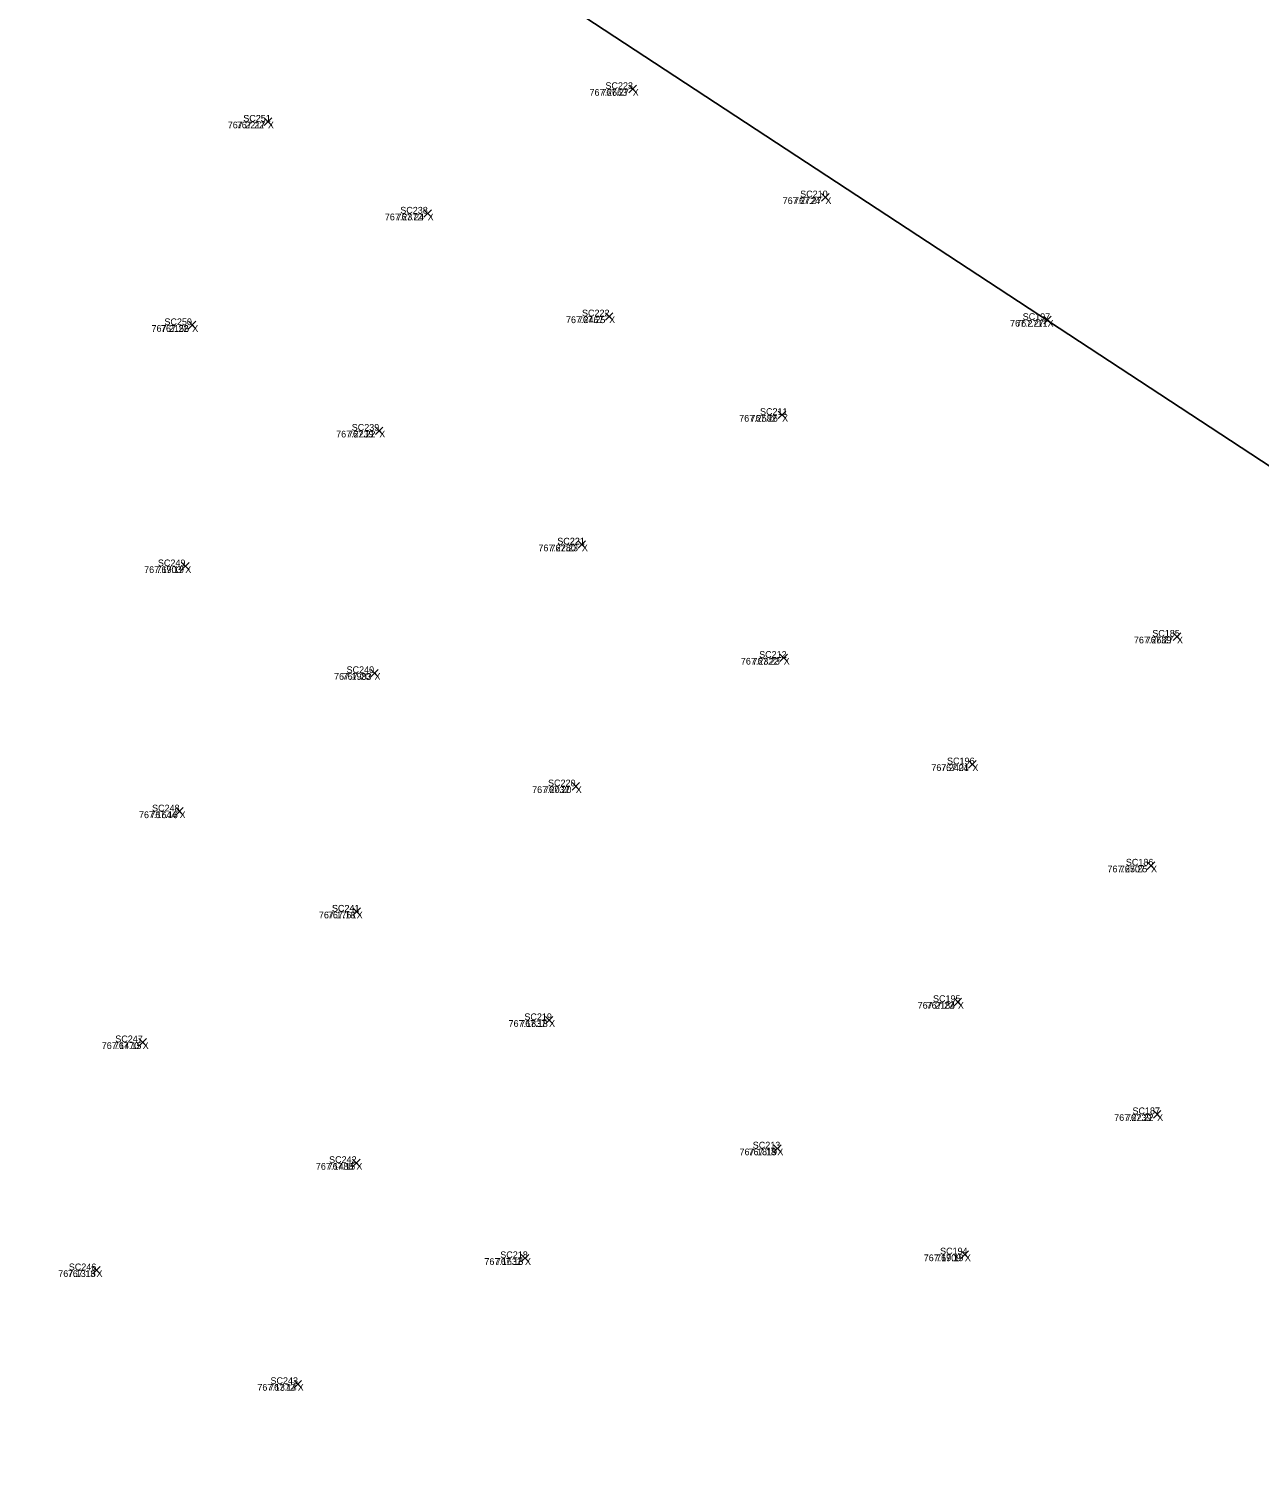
# Model space of a CAD drawing. Extents: x 1845019 to 1877956, y 680444 to 701081.
# Drawn here: x 1857662.57 to 1857673.54, y 694264.34 to 694277.24 of the extents above; entities that cross this region are included whole.
import ezdxf

# ---------------------------------------------------------------- set-up
doc = ezdxf.new("R2010")
doc.units = 0
for name, color, linetype in [('SV_X_CL_Survey_20', 7, 'Continuous'), ('SV_X_Random_Point', 7, 'Continuous'), ('SV_X_Text_Comment', 7, 'Continuous'), ('SV_X_Text_Elevation', 7, 'Continuous'), ('SV_X_Text_Name', 7, 'Continuous')]:
    doc.layers.add(name, color=color, linetype=linetype)

msp = doc.modelspace()

# ---------------------------------------------------------------- linework, layer by layer
at = {"layer": 'SV_X_CL_Survey_20'}
msp.add_line((1856038.267, 695346.314), (1858797.327, 693536.085), dxfattribs=at)
at = {"layer": 'SV_X_Random_Point'}
for p, q in [((1857667.919, 694276.675), (1857667.986, 694276.742)), ((1857667.919, 694276.742), (1857667.986, 694276.675)), ((1857667.919, 694276.675), (1857667.986, 694276.742)), ((1857667.919, 694276.742), (1857667.986, 694276.675)), ((1857664.666, 694276.384), (1857664.733, 694276.451)), ((1857664.666, 694276.451), (1857664.733, 694276.384)), ((1857664.666, 694276.384), (1857664.733, 694276.451)), ((1857664.666, 694276.451), (1857664.733, 694276.384)), ((1857669.638, 694275.709), (1857669.705, 694275.776)), ((1857669.638, 694275.776), (1857669.705, 694275.709)), ((1857669.638, 694275.709), (1857669.705, 694275.776)), ((1857669.638, 694275.776), (1857669.705, 694275.709)), ((1857666.091, 694275.564), (1857666.158, 694275.63)), ((1857666.091, 694275.63), (1857666.158, 694275.564)), ((1857666.091, 694275.564), (1857666.158, 694275.63)), ((1857666.091, 694275.63), (1857666.158, 694275.564)), ((1857663.991, 694274.569), (1857664.057, 694274.636)), ((1857663.991, 694274.636), (1857664.057, 694274.569)), ((1857663.991, 694274.569), (1857664.057, 694274.636)), ((1857663.991, 694274.636), (1857664.057, 694274.569)), ((1857667.71, 694274.646), (1857667.776, 694274.713)), ((1857667.71, 694274.713), (1857667.776, 694274.646)), ((1857667.71, 694274.646), (1857667.776, 694274.713)), ((1857667.71, 694274.713), (1857667.776, 694274.646)), ((1857671.62, 694274.614), (1857671.687, 694274.681)), ((1857671.62, 694274.681), (1857671.687, 694274.614)), ((1857671.62, 694274.614), (1857671.687, 694274.681)), ((1857671.62, 694274.681), (1857671.687, 694274.614)), ((1857669.252, 694273.768), (1857669.319, 694273.834)), ((1857669.252, 694273.834), (1857669.319, 694273.768)), ((1857669.252, 694273.768), (1857669.319, 694273.834)), ((1857669.252, 694273.834), (1857669.319, 694273.768)), ((1857665.658, 694273.627), (1857665.725, 694273.693)), ((1857665.658, 694273.693), (1857665.725, 694273.627)), ((1857665.658, 694273.627), (1857665.725, 694273.693)), ((1857665.658, 694273.693), (1857665.725, 694273.627)), ((1857667.466, 694272.612), (1857667.533, 694272.679)), ((1857667.466, 694272.679), (1857667.533, 694272.612)), ((1857667.466, 694272.612), (1857667.533, 694272.679)), ((1857667.466, 694272.679), (1857667.533, 694272.612)), ((1857663.929, 694272.418), (1857663.996, 694272.484)), ((1857663.929, 694272.484), (1857663.996, 694272.418)), ((1857663.929, 694272.418), (1857663.996, 694272.484)), ((1857663.929, 694272.484), (1857663.996, 694272.418)), ((1857672.775, 694271.79), (1857672.842, 694271.856)), ((1857672.775, 694271.856), (1857672.842, 694271.79)), ((1857672.775, 694271.79), (1857672.842, 694271.856)), ((1857672.775, 694271.856), (1857672.842, 694271.79)), ((1857669.267, 694271.601), (1857669.334, 694271.668)), ((1857669.267, 694271.668), (1857669.334, 694271.601)), ((1857669.267, 694271.601), (1857669.334, 694271.668)), ((1857669.267, 694271.668), (1857669.334, 694271.601)), ((1857665.617, 694271.465), (1857665.683, 694271.531)), ((1857665.617, 694271.531), (1857665.683, 694271.465)), ((1857665.617, 694271.465), (1857665.683, 694271.531)), ((1857665.617, 694271.531), (1857665.683, 694271.465)), ((1857670.949, 694270.651), (1857671.016, 694270.718)), ((1857670.949, 694270.718), (1857671.016, 694270.651)), ((1857670.949, 694270.651), (1857671.016, 694270.718)), ((1857670.949, 694270.718), (1857671.016, 694270.651)), ((1857667.412, 694270.454), (1857667.479, 694270.521)), ((1857667.412, 694270.521), (1857667.479, 694270.454)), ((1857667.412, 694270.454), (1857667.479, 694270.521)), ((1857667.412, 694270.521), (1857667.479, 694270.454)), ((1857663.877, 694270.231), (1857663.944, 694270.298)), ((1857663.877, 694270.298), (1857663.944, 694270.231)), ((1857663.877, 694270.231), (1857663.944, 694270.298)), ((1857663.877, 694270.298), (1857663.944, 694270.231)), ((1857672.543, 694269.747), (1857672.61, 694269.814)), ((1857672.543, 694269.814), (1857672.61, 694269.747)), ((1857672.543, 694269.747), (1857672.61, 694269.814)), ((1857672.543, 694269.814), (1857672.61, 694269.747)), ((1857665.458, 694269.337), (1857665.525, 694269.404)), ((1857665.458, 694269.404), (1857665.525, 694269.337)), ((1857665.458, 694269.337), (1857665.525, 694269.404)), ((1857665.458, 694269.404), (1857665.525, 694269.337)), ((1857670.821, 694268.531), (1857670.887, 694268.597)), ((1857670.821, 694268.597), (1857670.887, 694268.531)), ((1857670.821, 694268.531), (1857670.887, 694268.597)), ((1857670.821, 694268.597), (1857670.887, 694268.531)), ((1857667.174, 694268.368), (1857667.241, 694268.435)), ((1857667.174, 694268.435), (1857667.241, 694268.368)), ((1857667.174, 694268.368), (1857667.241, 694268.435)), ((1857667.174, 694268.435), (1857667.241, 694268.368)), ((1857663.548, 694268.171), (1857663.615, 694268.238)), ((1857663.548, 694268.238), (1857663.615, 694268.171)), ((1857663.548, 694268.171), (1857663.615, 694268.238)), ((1857663.548, 694268.238), (1857663.615, 694268.171)), ((1857672.598, 694267.529), (1857672.665, 694267.596)), ((1857672.598, 694267.596), (1857672.665, 694267.529)), ((1857672.598, 694267.529), (1857672.665, 694267.596)), ((1857672.598, 694267.596), (1857672.665, 694267.529)), ((1857669.21, 694267.223), (1857669.277, 694267.29)), ((1857669.21, 694267.29), (1857669.277, 694267.223)), ((1857669.21, 694267.223), (1857669.277, 694267.29)), ((1857669.21, 694267.29), (1857669.277, 694267.223)), ((1857665.455, 694267.094), (1857665.522, 694267.161)), ((1857665.455, 694267.161), (1857665.522, 694267.094)), ((1857665.455, 694267.094), (1857665.522, 694267.161)), ((1857665.455, 694267.161), (1857665.522, 694267.094)), ((1857666.959, 694266.246), (1857667.026, 694266.313)), ((1857666.959, 694266.313), (1857667.026, 694266.246)), ((1857666.959, 694266.246), (1857667.026, 694266.313)), ((1857666.959, 694266.313), (1857667.026, 694266.246)), ((1857670.883, 694266.279), (1857670.95, 694266.345)), ((1857670.883, 694266.345), (1857670.95, 694266.279)), ((1857670.883, 694266.279), (1857670.95, 694266.345)), ((1857670.883, 694266.345), (1857670.95, 694266.279)), ((1857663.137, 694266.138), (1857663.204, 694266.205)), ((1857663.137, 694266.205), (1857663.204, 694266.138)), ((1857663.137, 694266.138), (1857663.204, 694266.205)), ((1857663.137, 694266.205), (1857663.204, 694266.138)), ((1857664.932, 694265.123), (1857664.999, 694265.189)), ((1857664.932, 694265.189), (1857664.999, 694265.123)), ((1857664.932, 694265.123), (1857664.999, 694265.189)), ((1857664.932, 694265.189), (1857664.999, 694265.123))]:
    msp.add_line(p, q, dxfattribs=at)

# ---------------------------------------------------------------- texts
at = {"layer": 'SV_X_Text_Comment'}
for p in [(1857667.953, 694276.648), (1857664.699, 694276.357), (1857669.672, 694275.682), (1857666.124, 694275.537), (1857667.743, 694274.62), (1857671.654, 694274.588), (1857664.024, 694274.542), (1857669.286, 694273.741), (1857665.692, 694273.6), (1857667.5, 694272.585), (1857663.962, 694272.391), (1857672.808, 694271.763), (1857669.3, 694271.574), (1857665.65, 694271.438), (1857670.983, 694270.624), (1857667.445, 694270.428), (1857663.911, 694270.204), (1857672.577, 694269.721), (1857665.491, 694269.31), (1857670.854, 694268.504), (1857667.207, 694268.342), (1857663.582, 694268.145), (1857672.631, 694267.503), (1857669.243, 694267.197), (1857665.488, 694267.068), (1857666.992, 694266.219), (1857670.916, 694266.252), (1857663.17, 694266.111), (1857664.965, 694265.096)]:
    msp.add_text('X', height=0.06, dxfattribs=at).set_placement(p)
at = {"layer": 'SV_X_Text_Elevation'}
for s, p in [('767.2663', (1857667.568, 694276.648)), ('767.27', (1857667.673, 694276.648)), ('767.2217', (1857664.341, 694276.357)), ('767.22', (1857664.421, 694276.357)), ('767.2724', (1857669.291, 694275.682)), ('767.27', (1857669.392, 694275.682)), ('767.2372', (1857665.742, 694275.537)), ('767.24', (1857665.846, 694275.537)), ('767.2467', (1857667.358, 694274.62)), ('767.25', (1857667.464, 694274.62)), ('767.2711', (1857671.319, 694274.588)), ('767.27', (1857671.374, 694274.588)), ('767.2156', (1857663.661, 694274.542)), ('767.22', (1857663.745, 694274.542)), ('767.2582', (1857668.903, 694273.741)), ('767.26', (1857669.003, 694273.741)), ('767.2239', (1857665.308, 694273.6)), ('767.22', (1857665.413, 694273.6)), ('767.2280', (1857667.112, 694272.585)), ('767.23', (1857667.22, 694272.585)), ('767.1903', (1857663.595, 694272.391)), ('767.19', (1857663.705, 694272.391)), ('767.2689', (1857672.424, 694271.763)), ('767.27', (1857672.529, 694271.763)), ('767.2322', (1857668.918, 694271.574)), ('767.23', (1857669.021, 694271.574)), ('767.1983', (1857665.289, 694271.438)), ('767.20', (1857665.366, 694271.438)), ('767.2401', (1857670.617, 694270.624)), ('767.24', (1857670.704, 694270.624)), ('767.2032', (1857667.056, 694270.428)), ('767.20', (1857667.161, 694270.428)), ('767.1644', (1857663.549, 694270.204)), ('767.16', (1857663.65, 694270.204)), ('767.2507', (1857672.188, 694269.721)), ('767.25', (1857672.298, 694269.721)), ('767.1761', (1857665.154, 694269.31)), ('767.18', (1857665.234, 694269.31)), ('767.2184', (1857670.495, 694268.504)), ('767.22', (1857670.575, 694268.504)), ('767.1837', (1857666.846, 694268.342)), ('767.18', (1857666.95, 694268.342)), ('767.1470', (1857663.217, 694268.145)), ('767.15', (1857663.325, 694268.145)), ('767.2239', (1857672.248, 694267.503)), ('767.22', (1857672.353, 694267.503)), ('767.1819', (1857668.906, 694267.197)), ('767.18', (1857668.986, 694267.197)), ('767.1488', (1857665.127, 694267.068)), ('767.15', (1857665.232, 694267.068)), ('767.1632', (1857666.63, 694266.219)), ('767.16', (1857666.732, 694266.219)), ('767.1909', (1857670.549, 694266.252)), ('767.19', (1857670.659, 694266.252)), ('767.1316', (1857662.829, 694266.111)), ('767.13', (1857662.914, 694266.111)), ('767.1372', (1857664.605, 694265.096)), ('767.14', (1857664.709, 694265.096))]:
    msp.add_text(s, height=0.06, dxfattribs=at).set_placement(p)
at = {"layer": 'SV_X_Text_Name'}
for s, p in [('SC223', (1857667.71, 694276.708)), ('SC223', (1857667.71, 694276.708)), ('SC251', (1857664.479, 694276.417)), ('SC251', (1857664.48, 694276.417)), ('SC210', (1857669.447, 694275.742)), ('SC210', (1857669.447, 694275.742)), ('SC238', (1857665.88, 694275.597)), ('SC238', (1857665.88, 694275.597)), ('SC250', (1857663.776, 694274.602)), ('SC250', (1857663.776, 694274.602)), ('SC222', (1857667.501, 694274.68)), ('SC222', (1857667.501, 694274.68)), ('SC197', (1857671.432, 694274.648)), ('SC197', (1857671.432, 694274.648)), ('SC211', (1857669.089, 694273.801)), ('SC211', (1857669.089, 694273.801)), ('SC239', (1857665.447, 694273.66)), ('SC239', (1857665.447, 694273.66)), ('SC221', (1857667.28, 694272.645)), ('SC221', (1857667.281, 694272.645)), ('SC249', (1857663.718, 694272.451)), ('SC249', (1857663.718, 694272.451)), ('SC185', (1857672.588, 694271.823)), ('SC185', (1857672.588, 694271.823)), ('SC212', (1857669.081, 694271.634)), ('SC212', (1857669.081, 694271.634)), ('SC240', (1857665.401, 694271.498)), ('SC240', (1857665.401, 694271.498)), ('SC196', (1857670.757, 694270.684)), ('SC196', (1857670.757, 694270.684)), ('SC220', (1857667.198, 694270.488)), ('SC220', (1857667.198, 694270.488)), ('SC248', (1857663.666, 694270.264)), ('SC248', (1857663.666, 694270.264)), ('SC186', (1857672.352, 694269.781)), ('SC186', (1857672.352, 694269.781)), ('SC241', (1857665.27, 694269.37)), ('SC241', (1857665.271, 694269.37)), ('SC195', (1857670.632, 694268.564)), ('SC195', (1857670.632, 694268.564)), ('SC219', (1857666.987, 694268.402)), ('SC219', (1857666.987, 694268.402)), ('SC247', (1857663.338, 694268.205)), ('SC247', (1857663.338, 694268.205)), ('SC187', (1857672.411, 694267.563)), ('SC187', (1857672.411, 694267.563)), ('SC213', (1857669.024, 694267.257)), ('SC213', (1857669.024, 694267.257)), ('SC242', (1857665.245, 694267.128)), ('SC242', (1857665.245, 694267.128)), ('SC194', (1857670.695, 694266.312)), ('SC194', (1857670.695, 694266.312)), ('SC246', (1857662.923, 694266.171)), ('SC246', (1857662.923, 694266.171)), ('SC218', (1857666.772, 694266.279)), ('SC218', (1857666.772, 694266.279)), ('SC243', (1857664.722, 694265.156)), ('SC243', (1857664.722, 694265.156))]:
    msp.add_text(s, height=0.06, dxfattribs=at).set_placement(p)

doc.saveas('drawing.dxf')
